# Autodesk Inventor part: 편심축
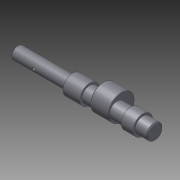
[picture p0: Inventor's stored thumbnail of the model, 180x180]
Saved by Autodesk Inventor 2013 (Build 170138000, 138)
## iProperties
Company: 한국ATC센터
Created: 2015-12
Part Number: 편심축
Document SubType Name: Modeling
Designer: mdu
Density: 7.86 g/cm^3
Mass: 222.98 g
Surface Area: 83.5896 cm^2
Volume: 28.3689 cm^3
Material: 강철, 연강
Author: mdu
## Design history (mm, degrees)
sketch "스케치1"
  geometry: L1 (-86, 0)-(86, 0); L2 (-86, 0)-(-86, 6); L3 (-86, 6)-(-32, 6); L4 (-32, 6)-(-32, 9.5); L5 (-32, 9.5)-(-15.5, 9.5); L6 (-15.5, 9.5)-(-15.5, 7.5); L7 (-15.5, 7.5)-(48, 7.5); L8 (86, 6)-(86, 0); L9 (36, 7.5)-(36, 9.5); L10 (36, 9.5)-(24.5, 9.5); L11 (24.5, 9.5)-(24.5, 7.5); L12 (48, 7.5)-(48, 6); L13 (48, 6)-(86, 6); 2 further points
  constraints: 26 end point, 6 parallel, 6 perpendicular, 2 point on line, 1 coincident, 1 horizontal, 1 midpoint
  dimensions: "d1" = 12 diameter of L3 L1; "d2" = 15 diameter of L7 L1; "d4" = 16.5 distance of L4.end L5.end; "d5" = 19 diameter of L5 L1; "d24" = 11.5 distance of L9.end L10.end; "d25" = 19 diameter of L10 L1; "d27" = 40 distance between parallel lines of L11 L6; "d28" = 54 distance of L2.end L3.end; "d29" = 50 distance between parallel lines of L8 L9; "d41" = 38 distance between parallel lines of L8 L12; "d42" = 12 diameter of L13 L1
revolve "회전1" stored, may be unused: angle "d6" = 90 deg
node "작업 평면1"
sketch "스케치2"
  geometry: C1 r 7.5 at (0, 0) reference; C2 r 12.5 at (0, 4.5); 1 further point
  constraints: 1 centre point, 1 vertical alignment
  dimensions: "d8" = 4.5 distance of point (0, 0) C2.centre; "d9" = 25 diameter of C2
extrude "돌출1" join sketch "스케치2" distance "d10" = 18; taper "d11" = 0 deg
chamfer "모따기1" distance "d12" = 1; stored, may be unused: second distance "d13" = 2, angle "d14" = 45 deg
chamfer "모따기2" distance "d15" = 0.5; stored, may be unused: second distance "d16" = 2, angle "d17" = 45 deg
node "작업 평면2"
sketch "스케치3"
  geometry: L1 (4, -2)-(18, -2); L2 (18, 2)-(4, 2); L3 (27, 5)-(27, -5) reference; A1 r 2 centre (18, 0) between (18, -2) and (18, 2); A2 r 2 centre (4, 0) between (4, 2) and (4, -2); 2 further points
  constraints: 4 end point, 4 point on circle, 4 tangent, 2 centre point, 1 horizontal, 1 horizontal alignment, 1 midpoint, 1 parallel
  dimensions: "d18" = 7 distance edge to line of A1 L3; "d19" = 4 distance between parallel lines of L2 L1; "d20" = 18 dimension on A1 A2
extrude "돌출2" cut sketch "스케치3" distance "d21" = 2.5; taper "d22" = 0 deg
revolve "회전2" stored, may be unused: angle "d26" = 90 deg
node "작업 평면3"
sketch "스케치4"
  geometry: L1 (44, 5)-(44, -5) reference; 2 further points
  constraints: 1 horizontal alignment
  dimensions: "d30" = 12 distance from line of point (32, 0) L1
hole "구멍1" sketch "스케치4" at (32, 0) diameter "d31" = 6; stored, may be unused: countersink angle "d35" = 90 deg, drill point angle "d37" = 118 deg; dims "d32" = 6, "d33" = 14, "d34" = 3, "d36" = 8
node "작업 평면4"
sketch "스케치5"
  geometry: C1 r 3 at (32, 0) reference; C2 r 8 at (32, 0); 2 further points
  constraints: 1 centre point, 1 coincident, 1 other
  dimensions: "d38" = 16 diameter of C2
extrude "돌출3" cut sketch "스케치5" distance "d39" = 3; taper "d40" = 0 deg
sketch "스케치6"
  geometry: L1 (-85, -6)-(-32, -6) reference; L2 (-86, -5)-(-86, 5) reference; L3 (-85, 6)-(-32, 6) reference; L4 (-64, 6)-(-64, -6); L5 (-64, -6)-(-62.5, -6); L6 (-64, -4.5)-(-62.5, -6); L7 (-64, -6)-(-64, -4.5); 2 further points
  constraints: 8 end point, 4 point on line, 2 perpendicular, 1 coincident
  dimensions: "d43" = 22 distance between parallel lines of L4 L2; "d44" = 45 deg angle of L6 L7; "d45" = 3 diameter of L5.end L4
revolve "회전3" stored, may be unused: angle "d46" = 90 deg
node "작업점1"
chamfer "모따기3" distance "d47" = 0.5; stored, may be unused: second distance "d48" = 2, angle "d49" = 45 deg
sketch "스케치7"
  geometry: C1 r 7.5 at (0, 0) reference; 1 further point
extrude "돌출4" cut sketch "스케치7" stored distance "d50" = 10; taper "d51" = 0 deg
chamfer "모따기4" distance "d52" = 1; stored, may be unused: second distance "d53" = 2, angle "d54" = 45 deg
node "작업 평면5"
hole "구멍2" diameter "d63" = 4.917; stored, may be unused: countersink angle "d67" = 90 deg, drill point angle "d69" = 118 deg; dims "d64" = 12, "d65" = 4, "d66" = 2, "d68" = 15, "d72" = 10, "d73" = 10
node "솔리드1"
node "투영된 루프1"
other parameters: "d7" = 8.5
